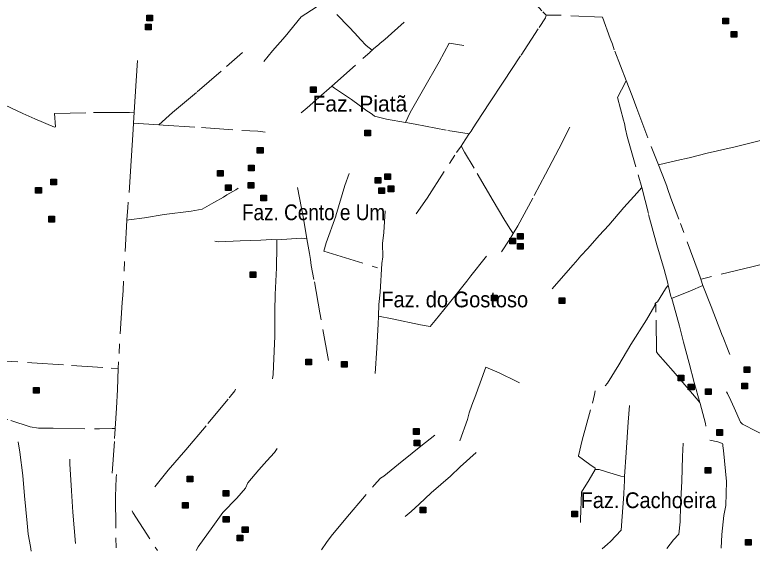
# Model space of a CAD drawing. Extents: x 393.5 to 446.9, y 8064.8 to 8120.4.
# Drawn here: x 405.95 to 413.44, y 8064.89 to 8070.34 of the extents above; entities that cross this region are included whole.
import ezdxf

# ---------------------------------------------------------------- set-up
doc = ezdxf.new("R2010")
doc.units = 0
doc.header["$LTSCALE"] = 0.064
doc.linetypes.add('DOT_DASHED', pattern=[7.7, 5, -1.2, 0.3, -1.2])
doc.layers.add('2', color=7, linetype='Continuous', lineweight=25)
doc.layers.add('22', color=7, linetype='DOT_DASHED', lineweight=13)
doc.layers.add('61', color=7, linetype='Continuous')

msp = doc.modelspace()

# ---------------------------------------------------------------- hatches: boundary and pattern name
at = {"layer": '2'}
for points in [[(407.2936, 8070.3361), (407.3516, 8070.3361), (407.3516, 8070.2781), (407.2936, 8070.2781)], [(413.1431, 8070.307), (413.2011, 8070.307), (413.2011, 8070.249), (413.1431, 8070.249)], [(407.2776, 8070.2435), (407.3356, 8070.2435), (407.3356, 8070.1855), (407.2776, 8070.1855)], [(413.2299, 8070.1702), (413.2879, 8070.1702), (413.2879, 8070.1122), (413.2299, 8070.1122)], [(408.9542, 8069.6089), (409.0122, 8069.6089), (409.0122, 8069.5509), (408.9542, 8069.5509)], [(409.507, 8069.1692), (409.565, 8069.1692), (409.565, 8069.1112), (409.507, 8069.1112)], [(408.4147, 8068.992), (408.4727, 8068.992), (408.4727, 8068.934), (408.4147, 8068.934)], [(408.3259, 8068.8133), (408.3839, 8068.8133), (408.3839, 8068.7553), (408.3259, 8068.7553)], [(408.0116, 8068.7589), (408.0696, 8068.7589), (408.0696, 8068.7009), (408.0116, 8068.7009)], [(409.71, 8068.724), (409.768, 8068.724), (409.768, 8068.666), (409.71, 8068.666)], [(406.3173, 8068.6713), (406.3753, 8068.6713), (406.3753, 8068.6133), (406.3173, 8068.6133)], [(408.323, 8068.6377), (408.381, 8068.6377), (408.381, 8068.5797), (408.323, 8068.5797)], [(409.612, 8068.6888), (409.67, 8068.6888), (409.67, 8068.6308), (409.612, 8068.6308)], [(406.1629, 8068.5875), (406.2209, 8068.5875), (406.2209, 8068.5295), (406.1629, 8068.5295)], [(408.0923, 8068.6136), (408.1503, 8068.6136), (408.1503, 8068.5556), (408.0923, 8068.5556)], [(409.6483, 8068.5821), (409.7063, 8068.5821), (409.7063, 8068.5241), (409.6483, 8068.5241)], [(409.745, 8068.6013), (409.803, 8068.6013), (409.803, 8068.5433), (409.745, 8068.5433)], [(408.4497, 8068.5075), (408.5077, 8068.5075), (408.5077, 8068.4495), (408.4497, 8068.4495)], [(406.2968, 8068.2934), (406.3548, 8068.2934), (406.3548, 8068.2354), (406.2968, 8068.2354)], [(411.0576, 8068.12), (411.1156, 8068.12), (411.1156, 8068.062), (411.0576, 8068.062)], [(410.979, 8068.0711), (411.037, 8068.0711), (411.037, 8068.0131), (410.979, 8068.0131)], [(411.0576, 8068.0183), (411.1156, 8068.0183), (411.1156, 8067.9603), (411.0576, 8067.9603)], [(408.3407, 8067.73), (408.3987, 8067.73), (408.3987, 8067.672), (408.3407, 8067.672)], [(410.7942, 8067.4927), (410.8522, 8067.4927), (410.8522, 8067.4347), (410.7942, 8067.4347)], [(411.481, 8067.4652), (411.539, 8067.4652), (411.539, 8067.4072), (411.481, 8067.4072)], [(408.9069, 8066.8435), (408.9649, 8066.8435), (408.9649, 8066.7855), (408.9069, 8066.7855)], [(409.2697, 8066.8186), (409.3277, 8066.8186), (409.3277, 8066.7606), (409.2697, 8066.7606)], [(413.362, 8066.7656), (413.42, 8066.7656), (413.42, 8066.7076), (413.362, 8066.7076)], [(412.6907, 8066.681), (412.7487, 8066.681), (412.7487, 8066.623), (412.6907, 8066.623)], [(406.1395, 8066.5566), (406.1975, 8066.5566), (406.1975, 8066.4986), (406.1395, 8066.4986)], [(412.7936, 8066.5893), (412.8516, 8066.5893), (412.8516, 8066.5313), (412.7936, 8066.5313)], [(412.969, 8066.5406), (413.027, 8066.5406), (413.027, 8066.4826), (412.969, 8066.4826)], [(413.3377, 8066.5992), (413.3957, 8066.5992), (413.3957, 8066.5412), (413.3377, 8066.5412)], [(410.0013, 8066.1372), (410.0593, 8066.1372), (410.0593, 8066.0792), (410.0013, 8066.0792)], [(413.0843, 8066.1271), (413.1423, 8066.1271), (413.1423, 8066.0691), (413.0843, 8066.0691)], [(410.0075, 8066.0216), (410.0655, 8066.0216), (410.0655, 8065.9636), (410.0075, 8065.9636)], [(412.9637, 8065.7432), (413.0217, 8065.7432), (413.0217, 8065.6852), (412.9637, 8065.6852)], [(407.7025, 8065.6559), (407.7605, 8065.6559), (407.7605, 8065.5979), (407.7025, 8065.5979)], [(408.0681, 8065.5099), (408.1261, 8065.5099), (408.1261, 8065.4519), (408.0681, 8065.4519)], [(407.6546, 8065.3882), (407.7126, 8065.3882), (407.7126, 8065.3302), (407.6546, 8065.3302)], [(410.0689, 8065.3402), (410.1269, 8065.3402), (410.1269, 8065.2822), (410.0689, 8065.2822)], [(411.61, 8065.2995), (411.668, 8065.2995), (411.668, 8065.2415), (411.61, 8065.2415)], [(408.0696, 8065.2442), (408.1276, 8065.2442), (408.1276, 8065.1862), (408.0696, 8065.1862)], [(408.2624, 8065.141), (408.3204, 8065.141), (408.3204, 8065.083), (408.2624, 8065.083)], [(408.2114, 8065.0564), (408.2694, 8065.0564), (408.2694, 8064.9984), (408.2114, 8064.9984)], [(413.3756, 8065.0128), (413.4336, 8065.0128), (413.4336, 8064.9548), (413.3756, 8064.9548)]]:
    msp.add_hatch(color=256, dxfattribs=at).paths.add_polyline_path(points)

# ---------------------------------------------------------------- linework, layer by layer
for points in [[(407.2936, 8070.3361), (407.3516, 8070.3361), (407.3516, 8070.2781), (407.2936, 8070.2781)], [(413.1431, 8070.307), (413.2011, 8070.307), (413.2011, 8070.249), (413.1431, 8070.249)], [(407.2776, 8070.2435), (407.3356, 8070.2435), (407.3356, 8070.1855), (407.2776, 8070.1855)], [(413.2299, 8070.1702), (413.2879, 8070.1702), (413.2879, 8070.1122), (413.2299, 8070.1122)], [(408.9542, 8069.6089), (409.0122, 8069.6089), (409.0122, 8069.5509), (408.9542, 8069.5509)], [(409.507, 8069.1692), (409.565, 8069.1692), (409.565, 8069.1112), (409.507, 8069.1112)], [(408.4147, 8068.992), (408.4727, 8068.992), (408.4727, 8068.934), (408.4147, 8068.934)], [(408.3259, 8068.8133), (408.3839, 8068.8133), (408.3839, 8068.7553), (408.3259, 8068.7553)], [(408.0116, 8068.7589), (408.0696, 8068.7589), (408.0696, 8068.7009), (408.0116, 8068.7009)], [(409.71, 8068.724), (409.768, 8068.724), (409.768, 8068.666), (409.71, 8068.666)], [(406.3173, 8068.6713), (406.3753, 8068.6713), (406.3753, 8068.6133), (406.3173, 8068.6133)], [(408.323, 8068.6377), (408.381, 8068.6377), (408.381, 8068.5797), (408.323, 8068.5797)], [(409.612, 8068.6888), (409.67, 8068.6888), (409.67, 8068.6308), (409.612, 8068.6308)], [(406.1629, 8068.5875), (406.2209, 8068.5875), (406.2209, 8068.5295), (406.1629, 8068.5295)], [(408.0923, 8068.6136), (408.1503, 8068.6136), (408.1503, 8068.5556), (408.0923, 8068.5556)], [(409.6483, 8068.5821), (409.7063, 8068.5821), (409.7063, 8068.5241), (409.6483, 8068.5241)], [(409.745, 8068.6013), (409.803, 8068.6013), (409.803, 8068.5433), (409.745, 8068.5433)], [(408.4497, 8068.5075), (408.5077, 8068.5075), (408.5077, 8068.4495), (408.4497, 8068.4495)], [(406.2968, 8068.2934), (406.3548, 8068.2934), (406.3548, 8068.2354), (406.2968, 8068.2354)], [(411.0576, 8068.12), (411.1156, 8068.12), (411.1156, 8068.062), (411.0576, 8068.062)], [(410.979, 8068.0711), (411.037, 8068.0711), (411.037, 8068.0131), (410.979, 8068.0131)], [(411.0576, 8068.0183), (411.1156, 8068.0183), (411.1156, 8067.9603), (411.0576, 8067.9603)], [(408.3407, 8067.73), (408.3987, 8067.73), (408.3987, 8067.672), (408.3407, 8067.672)], [(410.7942, 8067.4927), (410.8522, 8067.4927), (410.8522, 8067.4347), (410.7942, 8067.4347)], [(411.481, 8067.4652), (411.539, 8067.4652), (411.539, 8067.4072), (411.481, 8067.4072)], [(408.9069, 8066.8435), (408.9649, 8066.8435), (408.9649, 8066.7855), (408.9069, 8066.7855)], [(409.2697, 8066.8186), (409.3277, 8066.8186), (409.3277, 8066.7606), (409.2697, 8066.7606)], [(413.362, 8066.7656), (413.42, 8066.7656), (413.42, 8066.7076), (413.362, 8066.7076)], [(412.6907, 8066.681), (412.7487, 8066.681), (412.7487, 8066.623), (412.6907, 8066.623)], [(406.1395, 8066.5566), (406.1975, 8066.5566), (406.1975, 8066.4986), (406.1395, 8066.4986)], [(412.7936, 8066.5893), (412.8516, 8066.5893), (412.8516, 8066.5313), (412.7936, 8066.5313)], [(412.969, 8066.5406), (413.027, 8066.5406), (413.027, 8066.4826), (412.969, 8066.4826)], [(413.3377, 8066.5992), (413.3957, 8066.5992), (413.3957, 8066.5412), (413.3377, 8066.5412)], [(410.0013, 8066.1372), (410.0593, 8066.1372), (410.0593, 8066.0792), (410.0013, 8066.0792)], [(413.0843, 8066.1271), (413.1423, 8066.1271), (413.1423, 8066.0691), (413.0843, 8066.0691)], [(410.0075, 8066.0216), (410.0655, 8066.0216), (410.0655, 8065.9636), (410.0075, 8065.9636)], [(412.9637, 8065.7432), (413.0217, 8065.7432), (413.0217, 8065.6852), (412.9637, 8065.6852)], [(407.7025, 8065.6559), (407.7605, 8065.6559), (407.7605, 8065.5979), (407.7025, 8065.5979)], [(408.0681, 8065.5099), (408.1261, 8065.5099), (408.1261, 8065.4519), (408.0681, 8065.4519)], [(407.6546, 8065.3882), (407.7126, 8065.3882), (407.7126, 8065.3302), (407.6546, 8065.3302)], [(410.0689, 8065.3402), (410.1269, 8065.3402), (410.1269, 8065.2822), (410.0689, 8065.2822)], [(411.61, 8065.2995), (411.668, 8065.2995), (411.668, 8065.2415), (411.61, 8065.2415)], [(408.0696, 8065.2442), (408.1276, 8065.2442), (408.1276, 8065.1862), (408.0696, 8065.1862)], [(408.2624, 8065.141), (408.3204, 8065.141), (408.3204, 8065.083), (408.2624, 8065.083)], [(408.2114, 8065.0564), (408.2694, 8065.0564), (408.2694, 8064.9984), (408.2114, 8064.9984)], [(413.3756, 8065.0128), (413.4336, 8065.0128), (413.4336, 8064.9548), (413.3756, 8064.9548)]]:
    msp.add_lwpolyline(points, close=True, dxfattribs=at)
at = {"layer": '22'}
for p, q in [((412.1614, 8069.6718), (412.1396, 8069.6213)), ((407.1575, 8069.2397), (407.1642, 8069.3495)), ((407.1575, 8069.2397), (407.4151, 8069.2207)), ((409.919, 8069.2459), (409.9223, 8069.2453)), ((410.5668, 8069.1297), (410.5659, 8069.1283)), ((409.7132, 8068.3498), (409.7013, 8068.1296)), ((412.9428, 8067.5913), (412.922, 8067.6561)), ((411.949, 8066.5703), (411.971, 8066.5985)), ((411.8489, 8065.7229), (411.8489, 8065.7247)), ((411.8489, 8065.7229), (411.8542, 8065.7227)), ((412.1453, 8065.6407), (412.146, 8065.6508))]:
    msp.add_line(p, q, dxfattribs=at)
for points in [[(410.759, 8070.9893), (410.7786, 8070.965), (410.8331, 8070.9139), (411.0934, 8070.6168), (411.3147, 8070.3701), (411.3485, 8070.3349)], [(408.4822, 8069.8662), (408.5704, 8069.9753), (408.6968, 8070.1177), (408.8606, 8070.3203), (409.0143, 8070.4173), (409.0946, 8070.4726)], [(409.2235, 8070.3442), (409.3447, 8070.2185), (409.4056, 8070.153)], [(410.5668, 8069.1297), (410.5878, 8069.1569), (410.6066, 8069.1925), (410.6464, 8069.251), (410.7751, 8069.4459), (410.912, 8069.6558), (411.0943, 8069.9287), (411.2771, 8070.2105), (411.3411, 8070.3091), (411.3485, 8070.3349)], [(412.0229, 8070.041), (412.001, 8070.1), (411.9209, 8070.3144), (411.4949, 8070.3349), (411.3513, 8070.3349), (411.3496, 8070.3349), (411.3485, 8070.3349)], [(409.9075, 8070.2636), (409.7778, 8070.1486), (409.7108, 8070.0879), (409.6626, 8070.0503), (409.6471, 8070.0348), (409.5999, 8069.998), (409.581, 8069.9792)], [(409.4056, 8070.153), (409.4638, 8070.09), (409.5203, 8070.0294), (409.581, 8069.9792)], [(409.919, 8069.2459), (409.9672, 8069.3476), (410.1022, 8069.5837), (410.2632, 8069.8625), (410.3655, 8070.0503), (410.5146, 8070.0294)], [(412.1614, 8069.6718), (412.0415, 8069.9854), (412.0229, 8070.041)], [(407.4151, 8069.2207), (407.5524, 8069.3461), (407.8041, 8069.5573), (408.1002, 8069.8135), (408.2114, 8069.9079), (408.2645, 8069.9559)], [(409.1724, 8069.615), (409.5622, 8069.9624), (409.5765, 8069.9751), (409.581, 8069.9792)], [(407.1642, 8069.3495), (407.1836, 8069.6693), (407.197, 8069.8764)], [(405.3719, 8069.6417), (405.4554, 8069.6033), (405.6113, 8069.5378), (405.7855, 8069.4538), (406.0336, 8069.3389), (406.1558, 8069.2823), (406.3561, 8069.1991), (406.365, 8069.2026), (406.3543, 8069.3372), (406.7496, 8069.346), (406.8398, 8069.3465)], [(408.8616, 8069.3444), (408.9202, 8069.3946), (409.0395, 8069.4991), (409.1724, 8069.615)], [(409.5617, 8069.3426), (409.5283, 8069.3659), (409.3714, 8069.4809), (409.2006, 8069.5932), (409.1724, 8069.615)], [(412.1396, 8069.6213), (412.1146, 8069.5779), (412.0754, 8069.5006), (412.1362, 8069.2704), (412.1458, 8069.2355)], [(412.1614, 8069.6718), (412.2217, 8069.517), (412.2705, 8069.3885), (412.4171, 8069.0019), (412.4913, 8068.8155)], [(406.8398, 8069.3465), (406.8996, 8069.3477), (407.1177, 8069.3475), (407.1642, 8069.3495)], [(409.919, 8069.2459), (409.7266, 8069.2783), (409.6053, 8069.3092), (409.5839, 8069.3282), (409.5617, 8069.3426)], [(407.1575, 8069.2397), (407.1536, 8069.1741), (407.1337, 8068.8552), (407.1007, 8068.3826), (407.0893, 8068.2563), (407.0891, 8068.2542)], [(409.9223, 8069.2453), (410.0199, 8069.2279), (410.3507, 8069.1657), (410.5668, 8069.1297)], [(412.1458, 8069.2355), (412.1552, 8069.1772), (412.174, 8069.1023), (412.2848, 8068.7155), (412.3214, 8068.5862), (412.3227, 8068.5816), (412.3228, 8068.5811)], [(412.4913, 8068.8155), (412.6773, 8068.8613), (412.8028, 8068.8883), (412.9867, 8068.934), (413.2711, 8068.9984), (413.5805, 8069.0753), (413.9559, 8069.1589), (414.2612, 8069.2336), (414.3406, 8069.2502)], [(407.4151, 8069.2207), (407.4595, 8069.2175), (407.8479, 8069.1955), (408.2581, 8069.1663), (408.4193, 8069.1567), (408.4954, 8069.1488)], [(411.0151, 8068.1173), (411.062, 8068.1962), (411.2278, 8068.5038), (411.3412, 8068.7197), (411.4765, 8068.9782), (411.5901, 8069.197)], [(410.5659, 8069.1283), (410.5646, 8069.1264), (410.503, 8069.0316), (410.4851, 8069.0058)], [(410.0276, 8068.3174), (410.1389, 8068.4793), (410.4394, 8068.9406), (410.4851, 8069.0058)], [(411.0151, 8068.1173), (410.9811, 8068.1681), (410.9197, 8068.267), (410.8106, 8068.4521), (410.6174, 8068.7837), (410.5211, 8068.9447), (410.4881, 8069.0007), (410.4851, 8069.0058)], [(412.5755, 8068.5996), (412.5594, 8068.6442), (412.4913, 8068.8155)], [(409.3482, 8068.7291), (409.3048, 8068.6049), (409.2122, 8068.2942), (409.1153, 8068.0245), (409.0902, 8067.9408), (409.1802, 8067.9115), (409.6343, 8067.7693)], [(408.1066, 8068.5111), (408.1971, 8068.5621), (408.2213, 8068.5785)], [(408.9167, 8068.065), (408.8832, 8068.2704), (408.8183, 8068.6134)], [(411.6517, 8067.8314), (411.7019, 8067.8923), (411.7718, 8067.9656), (411.8876, 8068.0986), (411.9869, 8068.2044), (412.138, 8068.3834), (412.2725, 8068.5332), (412.3183, 8068.5828), (412.3214, 8068.5862)], [(412.5839, 8067.6138), (412.5467, 8067.7539), (412.4751, 8068.0023), (412.3875, 8068.3222), (412.3214, 8068.5862)], [(412.922, 8067.6561), (412.8949, 8067.7345), (412.6972, 8068.2639), (412.6147, 8068.4788), (412.5822, 8068.5762), (412.5755, 8068.5996)], [(407.0891, 8068.2542), (407.1103, 8068.256), (407.2699, 8068.2787), (407.4686, 8068.3112), (407.743, 8068.3471), (407.8552, 8068.3652), (407.9722, 8068.4343), (408.0697, 8068.4874), (408.1066, 8068.5111)], [(407.0891, 8068.2542), (407.0518, 8067.5438), (407.05, 8067.4916)], [(409.7013, 8068.1296), (409.6873, 8068.0188), (409.6894, 8067.8808), (409.681, 8067.8139), (409.6643, 8067.5232), (409.6498, 8067.3988), (409.6477, 8067.2796)], [(410.8973, 8067.9318), (410.9727, 8068.051), (411.012, 8068.1125), (411.0151, 8068.1173)], [(407.9827, 8068.0408), (408.0245, 8068.0345), (408.2422, 8068.0449), (408.4515, 8068.0512), (408.5582, 8068.0575), (408.6148, 8068.0533)], [(408.57, 8066.6436), (408.577, 8066.6856), (408.5803, 8066.7714), (408.5921, 8067.0752), (408.5919, 8067.3323), (408.5969, 8067.4985), (408.6106, 8067.7705), (408.6148, 8067.9906), (408.6148, 8068.0533)], [(408.9167, 8068.065), (408.8638, 8068.07), (408.6148, 8068.0533)], [(408.9554, 8067.8552), (408.945, 8067.9171), (408.9167, 8068.065)], [(410.5853, 8067.6876), (410.5984, 8067.7047), (410.7149, 8067.854), (410.7436, 8067.8885)], [(413.8716, 8067.8862), (413.6733, 8067.8377), (413.4388, 8067.7794), (412.9923, 8067.6724), (412.9237, 8067.6565), (412.922, 8067.6561)], [(409.1375, 8066.8297), (409.0504, 8067.3121), (408.9908, 8067.6529), (408.9626, 8067.7931), (408.9554, 8067.8552)], [(411.4092, 8067.5565), (411.6207, 8067.7979), (411.6517, 8067.8314)], [(409.6477, 8067.2796), (409.7837, 8067.2524), (410.0726, 8067.1897), (410.172, 8067.1731), (410.2216, 8067.2344), (410.3534, 8067.3991), (410.5423, 8067.6358), (410.5853, 8067.6876)], [(412.5885, 8067.5946), (412.5602, 8067.5573), (412.4806, 8067.4244), (412.4644, 8067.4135), (412.4597, 8067.4104), (412.4581, 8067.4093)], [(412.5839, 8067.6138), (412.5885, 8067.5946), (412.6164, 8067.4787), (412.6226, 8067.4648), (412.6232, 8067.4634)], [(412.6232, 8067.4634), (412.6402, 8067.4668), (412.8173, 8067.5349), (412.9428, 8067.5913)], [(412.9428, 8067.5913), (413.0273, 8067.3767), (413.1432, 8067.0743), (413.2024, 8066.9248), (413.2157, 8066.8908)], [(407.05, 8067.4916), (407.0428, 8067.419), (407.0048, 8066.8165), (407.0004, 8066.7492)], [(412.9109, 8066.402), (412.8543, 8066.6041), (412.8022, 8066.8031), (412.7463, 8067.0139), (412.7032, 8067.177), (412.6511, 8067.3751), (412.627, 8067.4589), (412.6232, 8067.4634)], [(412.2112, 8066.9923), (412.3687, 8067.2425), (412.4531, 8067.3871), (412.4581, 8067.4093)], [(412.9109, 8066.402), (412.8005, 8066.5356), (412.6393, 8066.7204), (412.4852, 8066.8961), (412.4705, 8066.9185), (412.465, 8067.319), (412.465, 8067.4007), (412.4603, 8067.4065), (412.4581, 8067.4093)], [(409.6122, 8066.6978), (409.6289, 8066.9534), (409.6435, 8067.2023), (409.6476, 8067.2774), (409.6477, 8067.2796)], [(411.971, 8066.5985), (412.0869, 8066.7847), (412.2112, 8066.9923)], [(405.329, 8066.8506), (405.3411, 8066.8494), (405.6618, 8066.8299), (406.1253, 8066.807), (406.5277, 8066.7794), (406.9287, 8066.7517), (406.9975, 8066.7493), (407.0004, 8066.7492)], [(410.6559, 8066.5386), (410.6792, 8066.6029), (410.7351, 8066.7622), (410.8736, 8066.7027), (411.0505, 8066.6143), (411.0793, 8066.6028)], [(406.9697, 8066.1394), (406.9845, 8066.3455), (406.9933, 8066.5332), (407.0004, 8066.7492)], [(407.3728, 8065.5467), (407.5097, 8065.7162), (407.688, 8065.922), (407.9138, 8066.1908), (408.1301, 8066.4493), (408.1868, 8066.5212), (408.194, 8066.5381)], [(410.5674, 8066.298), (410.5938, 8066.3767), (410.634, 8066.482), (410.6559, 8066.5386)], [(411.8489, 8065.7247), (411.8489, 8065.737), (411.7921, 8065.7717), (411.6791, 8065.8561), (411.6773, 8065.8596), (411.7166, 8066.0195), (411.8191, 8066.3945), (411.8413, 8066.4852), (411.8487, 8066.521)], [(413.586, 8066.0624), (413.4894, 8066.108), (413.3441, 8066.1815), (413.3249, 8066.2037), (413.2597, 8066.3487), (413.2265, 8066.4217), (413.1904, 8066.4942), (413.183, 8066.512)], [(412.9109, 8066.402), (412.9134, 8066.3932), (412.9673, 8066.1888), (412.9727, 8066.1611)], [(405.4163, 8066.3635), (405.4411, 8066.3668), (405.5742, 8066.3259), (405.9114, 8066.2196), (406.1078, 8066.1571), (406.1927, 8066.1425)], [(412.146, 8065.6508), (412.1624, 8065.8943), (412.1829, 8066.2023), (412.1977, 8066.373)], [(410.4715, 8066.0117), (410.5504, 8066.2313), (410.5674, 8066.298)], [(406.1927, 8066.1425), (406.3411, 8066.1404), (406.8129, 8066.1342), (406.9412, 8066.1377), (406.9697, 8066.1394)], [(406.9394, 8065.6862), (406.9654, 8066.0371), (406.9695, 8066.1358), (406.9696, 8066.1378), (406.9697, 8066.1394)], [(409.0666, 8064.9055), (409.1184, 8064.9815), (409.1652, 8065.045), (409.3141, 8065.2238), (409.6019, 8065.563), (409.6671, 8065.6349), (409.6989, 8065.655), (409.8478, 8065.7753), (409.9891, 8065.889), (410.0761, 8065.9575), (410.2175, 8066.0695)], [(413.0121, 8066.0207), (413.0923, 8066.0026), (413.1414, 8065.9871), (413.144, 8065.9792), (413.1441, 8065.9611), (413.1514, 8065.9146), (413.1828, 8065.5992), (413.1736, 8065.3569), (413.1532, 8065.2536), (413.133, 8065.0612), (413.1284, 8064.9234)], [(405.9862, 8066.0029), (406.0012, 8065.8973), (406.0313, 8065.6626), (406.049, 8065.4563), (406.0778, 8065.1781), (406.0875, 8065.0657), (406.1096, 8064.9386), (406.1169, 8064.8921)], [(408.4296, 8065.7173), (408.51, 8065.8107), (408.5886, 8065.8942), (408.6167, 8065.9342)], [(412.7408, 8065.9897), (412.736, 8065.854), (412.7279, 8065.6046), (412.7147, 8065.3517), (412.71, 8065.1894), (412.6986, 8065.0668), (412.6441, 8065.0088), (412.5771, 8064.921)], [(409.9156, 8065.2446), (409.9775, 8065.2965), (410.0578, 8065.37), (410.1797, 8065.4847), (410.3765, 8065.655), (410.4767, 8065.7501), (410.6396, 8065.8943)], [(406.5101, 8065.828), (406.511, 8065.7813), (406.5264, 8065.5072), (406.5392, 8065.2887), (406.5761, 8064.8942)], [(407.7928, 8064.8998), (407.8148, 8064.936), (407.9642, 8065.1422), (408.0644, 8065.285), (408.2053, 8065.4308), (408.2938, 8065.534), (408.3183, 8065.5878), (408.3917, 8065.6758), (408.4296, 8065.7173)], [(411.8489, 8065.7229), (411.7866, 8065.6178), (411.708, 8065.4921), (411.6981, 8065.2142), (411.6981, 8065.1826)], [(411.8542, 8065.7227), (411.8875, 8065.7212), (411.9613, 8065.6983), (412.1071, 8065.6562), (412.146, 8065.6508)], [(406.9839, 8065.6716), (406.9795, 8065.6384), (406.9733, 8065.4469), (406.9808, 8064.8961)], [(412.1453, 8065.6407), (412.1448, 8065.6339), (412.1405, 8065.5191), (412.1393, 8065.5046)], [(412.1393, 8065.5046), (412.137, 8065.4718), (412.1204, 8065.2453), (412.1116, 8065.1049), (412.0027, 8064.9908), (411.9711, 8064.9645), (411.9177, 8064.9182)], [(407.1437, 8065.3009), (407.1502, 8065.2858), (407.4013, 8064.898)]]:
    msp.add_lwpolyline(points, dxfattribs=at)

# ---------------------------------------------------------------- texts
at = {"layer": '61'}
msp.add_text('Faz. Piatã', height=0.16, dxfattribs=at).set_placement((408.9752, 8069.3573))
for s, width, p in [('Faz. Cento e Um', 0.9, (408.2588, 8068.2542)), ('Faz. do Gostoso', 0.95, (409.6747, 8067.3692)), ('Faz. Cachoeira', 0.95, (411.6991, 8065.3301))]:
    msp.add_text(s, height=0.16, dxfattribs=dict(at, width=width)).set_placement(p)

doc.saveas('drawing.dxf')
